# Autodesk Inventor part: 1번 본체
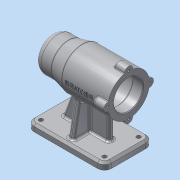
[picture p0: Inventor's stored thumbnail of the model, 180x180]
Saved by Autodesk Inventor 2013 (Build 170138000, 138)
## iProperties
Created: 2019-07
Part Number: 1번 본체
Material: 알루미늄 6061
Document SubType Name: Modeling
Designer: dgall
Density: 2.71 g/cm^3
Mass: 649.134 g
Surface Area: 655.8 cm^2
Volume: 239.533 cm^3
Author: dgall
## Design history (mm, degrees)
sketch "스케치1"
  geometry: L1 (-56, 35)-(56, 35); L2 (56, 35)-(56, -35); L3 (56, -35)-(-56, -35); L4 (-56, -35)-(-56, 35); 3 further points
  constraints: 8 end point, 2 midpoint, 2 parallel, 1 horizontal, 1 horizontal alignment, 1 perpendicular, 1 vertical alignment
  dimensions: "d0" = 112 distance of L1.start L1.end; "d1" = 70 distance of L3.end L1.start
extrude "돌출1" new body sketch "스케치1" distance "d2" = 10; taper "d3" = 0 deg
fillet "모깎기1" dims "d4" = 10
node "작업 평면1"
sketch "스케치2"
  geometry: L1 (-56, 80)-(56, 80); L2 (-56, 80)-(-56, 105); L3 (-56, 105)-(-31, 105); L4 (-31, 105)-(-11, 110); L5 (-11, 110)-(56, 110); L6 (56, 110)-(56, 80); 2 further points
  constraints: 12 end point, 3 horizontal, 2 vertical, 1 vertical alignment
  dimensions: "d6" = 112 distance of L1.start L1.end; "d7" = 80 distance from line of point (0, 0) L1; "d8" = 60 diameter of L5 L1; "d9" = 50 diameter of L3 L1; "d10" = 25 distance of L2.end L3.end; "d11" = 45 distance from line of L4.end L2
revolve "회전1" sketch "스케치2" stored, may be unused: angle "d12" = 90 deg
sketch "스케치3"
  geometry: L1 (-56, 55)-(-56, 105) reference; L2 (56, 50)-(56, 110) reference; L3 (-56, 80)-(56, 80); L4 (56, 101)-(41, 101); L5 (41, 101)-(41, 104); L6 (41, 104)-(-13, 104); L7 (-13, 104)-(-13, 101); L8 (-13, 101)-(-24.7, 101); L9 (-25, 100.7)-(-25, 97.5); L10 (-25, 97.5)-(-42.7, 97.5); L11 (-43, 97.2)-(-43, 96); L12 (-43, 96)-(-46.7, 96); L13 (-47, 95.7)-(-47, 90.5); L14 (-47, 90.5)-(-47, 90.5); L15 (-50, 87.5)-(-50, 80); L16 (56, 101)-(56, 80); A1 r 0.3 centre (-46.7, 95.7) between (-46.7, 96) and (-47, 95.7); A2 r 0.3 centre (-42.7, 97.2) between (-42.7, 97.5) and (-43, 97.2); A3 r 0.3 centre (-24.7, 100.7) between (-24.7, 101) and (-25, 100.7); A4 r 3 centre (-47, 87.5) between (-47, 90.5) and (-50, 87.5); 5 further points
  constraints: 28 end point, 10 point on line, 8 point on circle, 8 tangent, 6 vertical, 5 horizontal, 4 centre point, 2 equal radius, 2 midpoint, 2 perpendicular
  dimensions: "d13" = 42 diameter of L4 L3; "d15" = 48 diameter of L6 L3; "d16" = 42 diameter of L8 L3; "d17" = 35 diameter of L10 L3; "d18" = 32 diameter of L12 L3; "d19" = 21 diameter of L14 L3; "d20" = 3 distance of L13.end point (-50, 90.5); "d21" = 4 distance of L11.end point (-47, 96); "d22" = 18 distance of L9.end point (-43, 97.5); "d23" = 12 distance of L7.end point (-25, 101); "d24" = 54 distance of L5.end L6.end; "d25" = 15 distance of L4.start L4.end; "d26" = 0.3 radius of A1; "d27" = 3 radius of A4
revolve "회전2" sketch "스케치3" stored, may be unused: angle "d28" = 90 deg
fillet "모깎기2" dims "d29" = 3
sketch "스케치4"
  geometry: A1 r 30 centre (0, 0) between (-30, 0) and (-29.4, -5.97) reference; A2 r 6 centre (-30, 0) between (-29.4, 5.97) and (-29.4, -5.97); 1 further point
  constraints: 5 point on circle, 1 centre point
  dimensions: "d30" = 12 diameter of A2
extrude "돌출2" join sketch "스케치4" distance "d31" = 16; taper "d32" = 0 deg
fillet "모깎기3" dims "d36" = 10
fillet "모깎기4" dims "d37" = 3
sketch "스케치5"
  geometry: A1 r 6 centre (0, 0) between (0.6, 5.97) and (0.6, -5.97) reference; 2 further points
  constraints: 1 coincident
hole "구멍1" sketch "스케치5" at (0, 0) diameter "d38" = 3.242; stored, may be unused: countersink angle "d42" = 90 deg, drill point angle "d44" = 118 deg; dims "d39" = 8, "d40" = 4, "d41" = 2, "d43" = 11
fillet "모깎기5" dims "d48" = 3
fillet "모깎기6" dims "d49" = 1
fillet "모깎기7" dims "d50" = 3
fillet "모깎기8" dims "d51" = 1
chamfer "모따기1" distance "d52" = 1; stored, may be unused: second distance "d53" = 2, angle "d54" = 45 deg
sketch "스케치6"
  geometry: L1 (-46, 10)-(46, 10) reference; L2 (-56, 10)-(-46, 10) reference; L3 (-36, 10)-(-19.985, 54); L4 (-19.985, 54)-(31, 54); L5 (31, 54)-(31, 10); L6 (56, 10)-(56, 0) reference; L7 (-56, 0)-(-56, 10) reference; 1 further point
  constraints: 6 end point, 2 point on line, 1 horizontal, 1 vertical
  dimensions: "d55" = 25 distance between parallel lines of L6 L5; "d56" = 20 distance from line of L3.start L7; "d57" = 110 deg angle of L2 L3; "d58" = 54 distance from line of point (0, 0) L4
extrude "돌출3" join sketch "스케치6" stored distance "d59" = 8; taper "d60" = 0 deg
node "작업 평면2"
sketch "스케치7"
  geometry: L1 (-25, 10)-(25, 10) reference; L2 (25, 10)-(35, 10) reference; L3 (-35, 10)-(-25, 10) reference; L4 (-28, 10)-(-19.139, 60.253); L5 (28, 10)-(19.139, 60.253); L6 (-35, 0)-(-35, 10) reference; L7 (35, 10)-(35, 0) reference; C1 r 7.5 at (0, 80) reference; A1 r 27.5 centre (0, 80) between (-19.139, 60.253) and (19.139, 60.253); 1 further point
  constraints: 4 end point, 2 point on circle, 2 point on line, 1 centre point, 1 coincident
  dimensions: "d62" = 7 distance from line of L4.start L6; "d63" = 7 distance from line of L7 L5.start; "d64" = 100 deg angle of L2 L5; "d65" = 100 deg angle of L3 L4; "d66" = 55 diameter of A1
extrude "돌출4" join sketch "스케치7" stored distance "d67" = 8; taper "d68" = 0 deg
fillet "모깎기9" dims "d69" = 3
fillet "모깎기10" dims "d70" = 3
fillet "모깎기11" dims "d71" = 3
sketch "스케치8"
  geometry: A1 r 7 centre (-46, -25) between (-53, -25) and (-46, -32) reference; A2 r 7 centre (46, -25) between (46, -32) and (53, -25) reference; A3 r 7 centre (-46, 25) between (-46, 32) and (-53, 25) reference; 5 further points
  constraints: 3 coincident
hole "구멍2" sketch "스케치8" at (-46, 25), (-46, -25), (46, 24.425), (46, -25) diameter "d73" = 6; stored, may be unused: countersink angle "d77" = 90 deg, drill point angle "d79" = 118 deg; dims "d74" = 8, "d75" = 4, "d76" = 2, "d78" = 11
node "작업 평면3"
sketch "스케치9"
  geometry: L1 (33.5, 6.771)-(33.5, 29.226) reference; L2 (33.5, -5.998)-(33.5, 5.998) reference; 3 further points
  constraints: 1 horizontal alignment, 1 midpoint, 1 other
  dimensions: "d80" = 42 distance from line of L1 point (-8.5, 0)
feature "엠보싱1" sketch "스케치9" dims "d0" = 112, "d1" = 70, "d81" = 0.5, "d82" = 0
chamfer "모따기2" distance "d83" = 3; stored, may be unused: second distance "d84" = 2, angle "d85" = 45 deg
node "솔리드1"
pattern_circular "원형 패턴1" dims angle "d34" = 360 deg
pattern_circular "원형 패턴2" dims angle "d46" = 360 deg
other parameters: "d5" = 0, "d61" = 0
